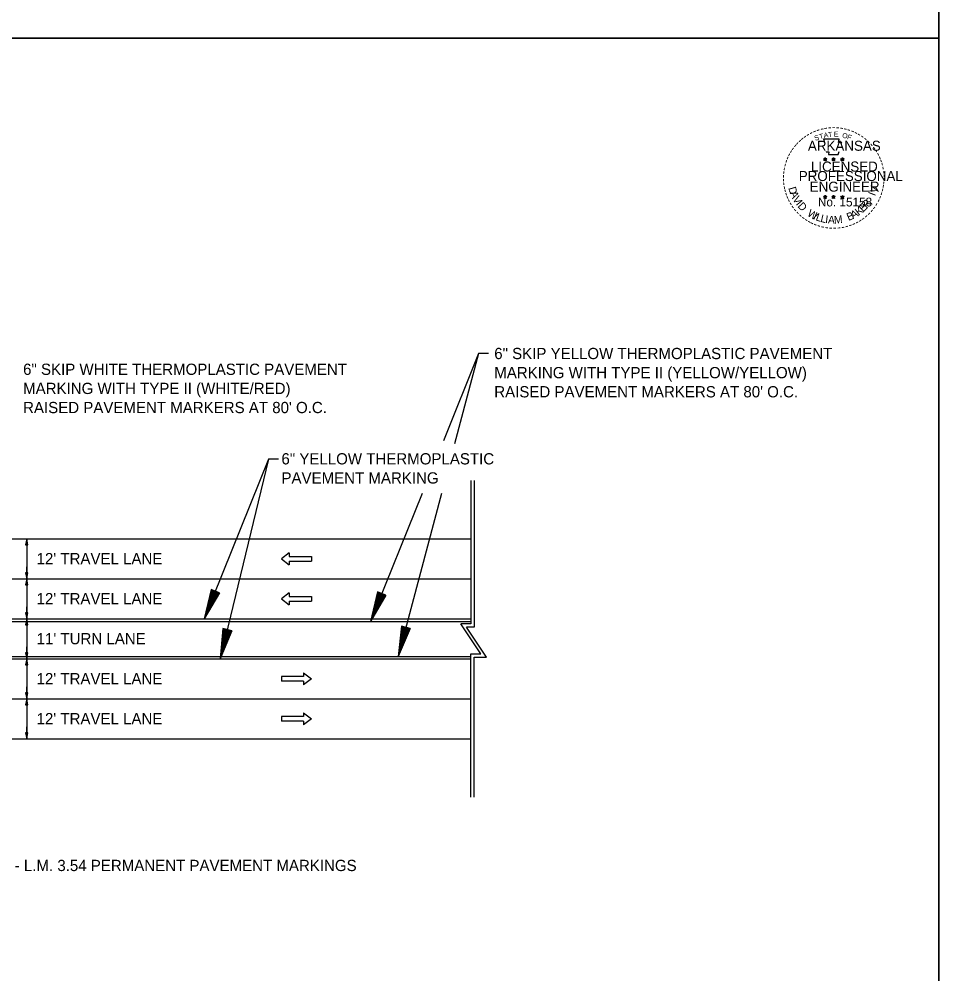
# Model space of a CAD drawing. Extents: x 1373096 to 1373266, y 381130 to 381790.
# Drawn here: x 1373174 to 1373266, y 381366.6 to 381462.1 of the extents above; entities that cross this region are included whole.
import ezdxf

# ---------------------------------------------------------------- set-up
doc = ezdxf.new("R2010")
doc.units = 0
for name, color, linetype in [('Default', 7, 'Continuous'), ('DSN_DRFT_Junk-No-Plot', 7, 'Continuous'), ('R_Border PE', 7, 'Continuous'), ('R_Draft', 7, 'Continuous')]:
    doc.layers.add(name, color=color, linetype=linetype)

msp = doc.modelspace()

# ---------------------------------------------------------------- linework, layer by layer
at = {"layer": 'Default'}
for p, q in [((1373219.95, 381428.656), (1373216.424, 381419.917)), ((1373219.95, 381428.656), (1373217.551, 381419.618)), ((1373220.95, 381428.656), (1373219.95, 381428.656)), ((1373198.936, 381418.092), (1373192.496, 381402.128)), ((1373198.936, 381418.092), (1373194.121, 381398.128)), ((1373199.936, 381418.092), (1373198.936, 381418.092)), ((1373219.169, 381415.965), (1373219.169, 381401.628)), ((1373219.502, 381415.965), (1373219.502, 381401.295)), ((1373214.305, 381414.664), (1373209.147, 381401.878)), ((1373216.238, 381414.671), (1373211.913, 381398.378)), ((1373201.021, 381408.728), (1373200.242, 381408.128)), ((1373201.021, 381408.728), (1373201.021, 381408.353)), ((1373200.242, 381408.128), (1373201.021, 381407.528)), ((1373201.021, 381408.353), (1373203.227, 381408.353)), ((1373201.021, 381407.903), (1373203.227, 381407.903)), ((1373201.021, 381407.903), (1373201.021, 381407.528)), ((1373203.227, 381408.353), (1373203.227, 381407.903)), ((1373193.201, 381405.078), (1373192.496, 381402.128)), ((1373193.271, 381405.05), (1373192.684, 381402.593)), ((1373193.342, 381405.022), (1373192.877, 381403.071)), ((1373193.411, 381404.994), (1373193.064, 381403.534)), ((1373194.036, 381404.742), (1373193.201, 381405.078)), ((1373193.482, 381404.965), (1373193.254, 381404.006)), ((1373193.553, 381404.936), (1373193.441, 381404.47)), ((1373193.684, 381404.884), (1373193.441, 381404.47)), ((1373194.036, 381404.742), (1373192.496, 381402.128)), ((1373193.966, 381404.77), (1373192.684, 381402.593)), ((1373193.895, 381404.798), (1373192.877, 381403.071)), ((1373193.826, 381404.826), (1373193.064, 381403.534)), ((1373193.754, 381404.856), (1373193.254, 381404.006)), ((1373201.021, 381404.728), (1373200.242, 381404.128)), ((1373200.242, 381404.128), (1373201.021, 381403.528)), ((1373201.021, 381404.728), (1373201.021, 381404.353)), ((1373201.021, 381404.353), (1373203.227, 381404.353)), ((1373203.227, 381404.353), (1373203.227, 381403.903)), ((1373209.852, 381404.828), (1373209.147, 381401.878)), ((1373210.687, 381404.492), (1373209.147, 381401.878)), ((1373209.922, 381404.8), (1373209.334, 381402.343)), ((1373210.617, 381404.52), (1373209.334, 381402.343)), ((1373209.993, 381404.772), (1373209.528, 381402.821)), ((1373210.546, 381404.548), (1373209.528, 381402.821)), ((1373210.062, 381404.744), (1373209.714, 381403.284)), ((1373210.477, 381404.576), (1373209.714, 381403.284)), ((1373210.687, 381404.492), (1373209.852, 381404.828)), ((1373210.133, 381404.715), (1373209.905, 381403.756)), ((1373210.404, 381404.606), (1373209.905, 381403.756)), ((1373210.204, 381404.686), (1373210.092, 381404.22)), ((1373210.335, 381404.634), (1373210.092, 381404.22)), ((1373201.021, 381403.903), (1373203.227, 381403.903)), ((1373201.021, 381403.903), (1373201.021, 381403.528)), ((1373194.387, 381401.15), (1373194.121, 381398.128)), ((1373194.46, 381401.132), (1373194.239, 381398.615)), ((1373194.535, 381401.114), (1373194.36, 381399.117)), ((1373195.262, 381400.939), (1373194.387, 381401.15)), ((1373194.608, 381401.097), (1373194.477, 381399.602)), ((1373194.682, 381401.079), (1373194.596, 381400.096)), ((1373212.248, 381401.393), (1373211.913, 381398.378)), ((1373213.118, 381401.162), (1373211.913, 381398.378)), ((1373212.32, 381401.374), (1373212.042, 381398.862)), ((1373213.045, 381401.181), (1373212.042, 381398.862)), ((1373212.394, 381401.354), (1373212.174, 381399.361)), ((1373212.971, 381401.201), (1373212.174, 381399.361)), ((1373213.118, 381401.162), (1373212.248, 381401.393)), ((1373212.467, 381401.335), (1373212.302, 381399.844)), ((1373212.899, 381401.22), (1373212.302, 381399.844)), ((1373212.541, 381401.315), (1373212.433, 381400.335)), ((1373212.823, 381401.24), (1373212.433, 381400.335)), ((1373212.615, 381401.296), (1373212.561, 381400.819)), ((1373212.751, 381401.259), (1373212.561, 381400.819)), ((1373219.169, 381401.628), (1373218.169, 381401.628)), ((1373220.169, 381398.628), (1373218.169, 381401.628)), ((1373220.725, 381398.295), (1373218.725, 381401.295)), ((1373219.502, 381401.295), (1373218.725, 381401.295)), ((1373195.262, 381400.939), (1373194.121, 381398.128)), ((1373195.189, 381400.956), (1373194.239, 381398.615)), ((1373195.115, 381400.974), (1373194.36, 381399.117)), ((1373195.042, 381400.992), (1373194.477, 381399.602)), ((1373194.966, 381401.01), (1373194.596, 381400.096)), ((1373194.756, 381401.061), (1373194.714, 381400.583)), ((1373194.893, 381401.028), (1373194.714, 381400.583)), ((1373219.169, 381384.291), (1373219.169, 381398.628)), ((1373219.169, 381398.628), (1373220.169, 381398.628)), ((1373219.502, 381384.291), (1373219.502, 381398.295)), ((1373219.502, 381398.295), (1373220.725, 381398.295)), ((1373202.449, 381396.353), (1373200.242, 381396.353)), ((1373200.242, 381396.353), (1373200.242, 381395.903)), ((1373202.449, 381396.728), (1373202.449, 381396.353)), ((1373202.449, 381396.728), (1373203.227, 381396.128)), ((1373202.449, 381395.903), (1373200.242, 381395.903)), ((1373203.227, 381396.128), (1373202.449, 381395.528)), ((1373202.449, 381395.903), (1373202.449, 381395.528)), ((1373202.449, 381392.728), (1373202.449, 381392.353)), ((1373202.449, 381392.728), (1373203.227, 381392.128)), ((1373202.449, 381392.353), (1373200.242, 381392.353)), ((1373200.242, 381392.353), (1373200.242, 381391.903)), ((1373202.449, 381391.903), (1373200.242, 381391.903)), ((1373203.227, 381392.128), (1373202.449, 381391.528)), ((1373202.449, 381391.903), (1373202.449, 381391.528))]:
    msp.add_line(p, q, dxfattribs=at)
for points in [[(1373095.974, 381570.174), (1373095.974, 381460.174), (1373265.974, 381460.174), (1373265.974, 381570.174)], [(1373095.974, 381460.174), (1373095.974, 381350.174), (1373265.974, 381350.174), (1373265.974, 381460.174)]]:
    msp.add_lwpolyline(points, close=True, dxfattribs=at)
at = {"layer": 'DSN_DRFT_Junk-No-Plot'}
msp.add_line((1373174.763, 381410.128), (1373174.763, 381390.154), dxfattribs=at)
for points in [[(1373095.974, 381570.174), (1373265.974, 381570.174), (1373265.974, 381460.174), (1373095.974, 381460.174)], [(1373095.974, 381570.174), (1373095.974, 381460.174), (1373265.974, 381460.174), (1373265.974, 381570.174)], [(1373095.974, 381460.174), (1373265.974, 381460.174), (1373265.974, 381350.174), (1373095.974, 381350.174)], [(1373095.974, 381460.174), (1373095.974, 381350.174), (1373265.974, 381350.174), (1373265.974, 381460.174)]]:
    msp.add_lwpolyline(points, close=True, dxfattribs=at)
for points in [[(1373174.763, 381410.128), (1373174.643, 381409.528), (1373174.883, 381409.528), (1373174.763, 381410.128), (1373174.763, 381408.928)], [(1373174.763, 381406.128), (1373174.883, 381406.728), (1373174.643, 381406.728), (1373174.763, 381406.128), (1373174.763, 381407.328)], [(1373174.763, 381406.128), (1373174.643, 381405.528), (1373174.883, 381405.528), (1373174.763, 381406.128), (1373174.763, 381404.928)], [(1373174.763, 381402.128), (1373174.883, 381402.728), (1373174.643, 381402.728), (1373174.763, 381402.128), (1373174.763, 381403.328)], [(1373174.763, 381402.128), (1373174.643, 381401.528), (1373174.883, 381401.528), (1373174.763, 381402.128), (1373174.763, 381400.928)], [(1373174.763, 381398.128), (1373174.883, 381398.728), (1373174.643, 381398.728), (1373174.763, 381398.128), (1373174.763, 381399.328)], [(1373174.763, 381398.128), (1373174.643, 381397.528), (1373174.883, 381397.528), (1373174.763, 381398.128), (1373174.763, 381396.928)], [(1373174.763, 381394.128), (1373174.883, 381394.728), (1373174.643, 381394.728), (1373174.763, 381394.128), (1373174.763, 381395.328)], [(1373174.763, 381394.128), (1373174.643, 381393.528), (1373174.883, 381393.528), (1373174.763, 381394.128), (1373174.763, 381392.928)], [(1373174.763, 381390.128), (1373174.883, 381390.728), (1373174.643, 381390.728), (1373174.763, 381390.128), (1373174.763, 381391.328)]]:
    msp.add_lwpolyline(points, dxfattribs=at)
at = {"layer": 'R_Border PE'}
for p, q in [((1373254.429, 381448.13), (1373254.603, 381448.074)), ((1373254.429, 381448.13), (1373254.555, 381448.107)), ((1373254.429, 381448.13), (1373254.547, 381448.069)), ((1373254.495, 381447.926), (1373254.603, 381448.074)), ((1373254.495, 381447.926), (1373254.558, 381448.048)), ((1373254.495, 381447.926), (1373254.602, 381448.034)), ((1373254.603, 381448.257), (1373254.583, 381448.131)), ((1373254.71, 381447.926), (1373254.602, 381448.033)), ((1373254.603, 381448.074), (1373254.603, 381448.257)), ((1373254.603, 381448.257), (1373254.628, 381448.132)), ((1373254.777, 381448.13), (1373254.603, 381448.074)), ((1373254.71, 381447.926), (1373254.603, 381448.074)), ((1373254.777, 381448.13), (1373254.634, 381448.105)), ((1373254.71, 381447.926), (1373254.641, 381448.071)), ((1373254.777, 381448.13), (1373254.675, 381448.079)), ((1373255.264, 381448.13), (1373255.438, 381448.074)), ((1373255.264, 381448.13), (1373255.39, 381448.107)), ((1373255.264, 381448.13), (1373255.382, 381448.069)), ((1373255.33, 381447.926), (1373255.438, 381448.074)), ((1373255.33, 381447.926), (1373255.393, 381448.048)), ((1373255.33, 381447.926), (1373255.437, 381448.034)), ((1373255.438, 381448.257), (1373255.418, 381448.131)), ((1373255.545, 381447.926), (1373255.437, 381448.033)), ((1373255.438, 381448.074), (1373255.438, 381448.257)), ((1373255.438, 381448.257), (1373255.463, 381448.132)), ((1373255.612, 381448.13), (1373255.438, 381448.074)), ((1373255.545, 381447.926), (1373255.438, 381448.074)), ((1373255.612, 381448.13), (1373255.469, 381448.105)), ((1373255.545, 381447.926), (1373255.476, 381448.071)), ((1373255.612, 381448.13), (1373255.51, 381448.079)), ((1373256.146, 381448.124), (1373256.32, 381448.068)), ((1373256.146, 381448.124), (1373256.272, 381448.101)), ((1373256.146, 381448.124), (1373256.264, 381448.063)), ((1373256.212, 381447.92), (1373256.32, 381448.068)), ((1373256.212, 381447.92), (1373256.275, 381448.042)), ((1373256.212, 381447.92), (1373256.319, 381448.028)), ((1373256.32, 381448.251), (1373256.3, 381448.125)), ((1373256.427, 381447.92), (1373256.319, 381448.027)), ((1373256.32, 381448.068), (1373256.32, 381448.251)), ((1373256.32, 381448.251), (1373256.345, 381448.126)), ((1373256.494, 381448.124), (1373256.32, 381448.068)), ((1373256.427, 381447.92), (1373256.32, 381448.068)), ((1373256.494, 381448.124), (1373256.351, 381448.099)), ((1373256.427, 381447.92), (1373256.358, 381448.065)), ((1373256.494, 381448.124), (1373256.392, 381448.073)), ((1373254.427, 381444.343), (1373254.601, 381444.288)), ((1373254.427, 381444.343), (1373254.553, 381444.321)), ((1373254.427, 381444.343), (1373254.545, 381444.282)), ((1373254.493, 381444.139), (1373254.601, 381444.288)), ((1373254.493, 381444.139), (1373254.556, 381444.261)), ((1373254.493, 381444.139), (1373254.6, 381444.248)), ((1373254.601, 381444.47), (1373254.581, 381444.344)), ((1373254.708, 381444.139), (1373254.6, 381444.246)), ((1373254.601, 381444.288), (1373254.601, 381444.47)), ((1373254.601, 381444.47), (1373254.626, 381444.345)), ((1373254.775, 381444.343), (1373254.601, 381444.288)), ((1373254.708, 381444.139), (1373254.601, 381444.288)), ((1373254.775, 381444.343), (1373254.632, 381444.319)), ((1373254.708, 381444.139), (1373254.639, 381444.285)), ((1373254.775, 381444.343), (1373254.673, 381444.292)), ((1373255.261, 381444.343), (1373255.436, 381444.288)), ((1373255.261, 381444.343), (1373255.388, 381444.321)), ((1373255.261, 381444.343), (1373255.38, 381444.282)), ((1373255.328, 381444.139), (1373255.436, 381444.288)), ((1373255.328, 381444.139), (1373255.391, 381444.261)), ((1373255.328, 381444.139), (1373255.435, 381444.248)), ((1373255.436, 381444.47), (1373255.415, 381444.344)), ((1373255.542, 381444.139), (1373255.435, 381444.246)), ((1373255.436, 381444.288), (1373255.436, 381444.47)), ((1373255.436, 381444.47), (1373255.46, 381444.345)), ((1373255.609, 381444.343), (1373255.436, 381444.288)), ((1373255.542, 381444.139), (1373255.436, 381444.288)), ((1373255.609, 381444.343), (1373255.466, 381444.319)), ((1373255.542, 381444.139), (1373255.474, 381444.285)), ((1373255.609, 381444.343), (1373255.507, 381444.292)), ((1373256.145, 381444.338), (1373256.319, 381444.283)), ((1373256.145, 381444.338), (1373256.271, 381444.316)), ((1373256.145, 381444.338), (1373256.263, 381444.277)), ((1373256.211, 381444.134), (1373256.319, 381444.283)), ((1373256.211, 381444.134), (1373256.274, 381444.256)), ((1373256.211, 381444.134), (1373256.318, 381444.243)), ((1373256.319, 381444.465), (1373256.299, 381444.339)), ((1373256.426, 381444.134), (1373256.318, 381444.241)), ((1373256.319, 381444.283), (1373256.319, 381444.465)), ((1373256.319, 381444.465), (1373256.344, 381444.34)), ((1373256.493, 381444.338), (1373256.319, 381444.283)), ((1373256.426, 381444.134), (1373256.319, 381444.283)), ((1373256.493, 381444.338), (1373256.35, 381444.314)), ((1373256.426, 381444.134), (1373256.357, 381444.28)), ((1373256.493, 381444.338), (1373256.391, 381444.287))]:
    msp.add_line(p, q, dxfattribs=at)
for points in [[(1373254.449, 381450.069), (1373254.584, 381449.655)], [(1373256.205, 381449.608), (1373256.276, 381449.75), (1373255.933, 381449.738), (1373256.007, 381450.069), (1373254.449, 381450.069)], [(1373254.695, 381448.857), (1373254.695, 381448.814), (1373254.977, 381448.804), (1373254.95, 381448.568), (1373255.885, 381448.568), (1373255.985, 381448.836)], [(1373254.603, 381448.257), (1373254.71, 381447.926), (1373254.429, 381448.13), (1373254.777, 381448.13), (1373254.495, 381447.926), (1373254.603, 381448.257)], [(1373255.438, 381448.257), (1373255.545, 381447.926), (1373255.264, 381448.13), (1373255.612, 381448.13), (1373255.33, 381447.926), (1373255.438, 381448.257)], [(1373256.32, 381448.251), (1373256.427, 381447.92), (1373256.146, 381448.124), (1373256.494, 381448.124), (1373256.212, 381447.92), (1373256.32, 381448.251)], [(1373254.601, 381444.47), (1373254.708, 381444.139), (1373254.427, 381444.343), (1373254.775, 381444.343), (1373254.493, 381444.139), (1373254.601, 381444.47)], [(1373255.436, 381444.47), (1373255.542, 381444.139), (1373255.261, 381444.343), (1373255.609, 381444.343), (1373255.328, 381444.139), (1373255.436, 381444.47)], [(1373256.319, 381444.465), (1373256.426, 381444.134), (1373256.145, 381444.338), (1373256.493, 381444.338), (1373256.211, 381444.134), (1373256.319, 381444.465)]]:
    msp.add_lwpolyline(points, dxfattribs=at)
for centre, radius in [((1373254.603, 381448.074), 0.0861), ((1373254.603, 381448.074), 0.0723), ((1373254.603, 381448.074), 0.0579), ((1373254.603, 381448.074), 0.0495), ((1373254.603, 381448.074), 0.0374), ((1373254.603, 381448.074), 0.0248), ((1373254.603, 381448.074), 0.0148), ((1373255.438, 381448.074), 0.0861), ((1373255.438, 381448.074), 0.0723), ((1373255.438, 381448.074), 0.0579), ((1373255.438, 381448.074), 0.0495), ((1373255.438, 381448.074), 0.0374), ((1373255.438, 381448.074), 0.0248), ((1373255.438, 381448.074), 0.0148), ((1373256.32, 381448.068), 0.0861), ((1373256.32, 381448.068), 0.0723), ((1373256.32, 381448.068), 0.0579), ((1373256.32, 381448.068), 0.0495), ((1373256.32, 381448.068), 0.0374), ((1373256.32, 381448.068), 0.0248), ((1373256.32, 381448.068), 0.0148), ((1373254.601, 381444.287), 0.0861), ((1373254.601, 381444.287), 0.0723), ((1373254.601, 381444.287), 0.0579), ((1373254.601, 381444.287), 0.0495), ((1373254.601, 381444.287), 0.0374), ((1373254.601, 381444.287), 0.0248), ((1373254.601, 381444.287), 0.0148), ((1373255.435, 381444.287), 0.0861), ((1373255.435, 381444.287), 0.0723), ((1373255.435, 381444.287), 0.0579), ((1373255.435, 381444.287), 0.0495), ((1373255.435, 381444.287), 0.0374), ((1373255.435, 381444.287), 0.0248), ((1373255.435, 381444.287), 0.0148), ((1373256.319, 381444.282), 0.0861), ((1373256.319, 381444.282), 0.0723), ((1373256.319, 381444.282), 0.0579), ((1373256.319, 381444.282), 0.0495), ((1373256.319, 381444.282), 0.0374), ((1373256.319, 381444.282), 0.0248), ((1373256.319, 381444.282), 0.0148)]:
    msp.add_circle(centre, radius, dxfattribs=at)
at = {"layer": 'R_Draft'}
for p, q in [((1373142.778, 381410.128), (1373219.169, 381410.128)), ((1373142.778, 381406.128), (1373219.169, 381406.128)), ((1373142.778, 381402.128), (1373219.169, 381402.128)), ((1373142.778, 381401.878), (1373219.169, 381401.878)), ((1373142.778, 381398.378), (1373219.169, 381398.378)), ((1373142.778, 381398.128), (1373219.169, 381398.128)), ((1373142.778, 381394.128), (1373219.169, 381394.128)), ((1373142.778, 381390.128), (1373219.169, 381390.128))]:
    msp.add_line(p, q, dxfattribs=at)

# ---------------------------------------------------------------- texts
at = {"layer": 'Default'}
for s, p in [('6" SKIP YELLOW THERMOPLASTIC PAVEMENT', (1373221.513, 381428.094)), ('6" SKIP WHITE THERMOPLASTIC PAVEMENT', (1373174.403, 381426.517)), ('MARKING WITH TYPE II (YELLOW/YELLOW)', (1373221.513, 381426.181)), ('MARKING WITH TYPE II (WHITE/RED)', (1373174.403, 381424.605)), ("RAISED PAVEMENT MARKERS AT 80' O.C.", (1373221.513, 381424.269)), ("RAISED PAVEMENT MARKERS AT 80' O.C.", (1373174.403, 381422.693)), ('6" YELLOW THERMOPLASTIC', (1373200.237, 381417.566)), ('PAVEMENT MARKING', (1373200.237, 381415.653))]:
    msp.add_text(s, height=1.125, dxfattribs=at).set_placement(p)
at = {"layer": 'R_Border PE'}
for s, height, rotation, p in [('-', 0.8, 28.79182, (1373253.189, 381450.339)), ('-', 0.8, 24.30721, (1373253.506, 381450.498)), ('-', 0.8, 19.17608, (1373253.823, 381450.632)), ('-', 0.8, 13.63015, (1373254.198, 381450.753)), ('A', 0.5, 11.21318, (1373254.496, 381450.199)), ('-', 0.8, 10.21935, (1373254.537, 381450.834)), ('T', 0.5, 6.02276, (1373254.921, 381450.282)), ('-', 0.8, 5.89682, (1373254.901, 381450.889)), ('-', 0.8, 0.18623, (1373255.287, 381450.925)), ('E', 0.5, 0.83234, (1373255.473, 381450.337)), ('-', 0.8, 357.74304, (1373255.649, 381450.918)), ('-', 0.8, 352.16172, (1373256.021, 381450.89)), ('O', 0.5, 350.4515, (1373256.275, 381450.232)), ('-', 0.8, 347.20489, (1373256.38, 381450.833)), ('-', 0.8, 342.3362, (1373256.698, 381450.756)), ('-', 0.8, 337.85509, (1373257.065, 381450.644)), ('-', 0.8, 334.12109, (1373257.381, 381450.509)), ('-', 0.8, 48.42305, (1373251.923, 381449.32)), ('-', 0.8, 42.96224, (1373252.147, 381449.559)), ('-', 0.8, 38.95066, (1373252.364, 381449.768)), ('-', 0.8, 36.23174, (1373252.602, 381449.957)), ('-', 0.8, 34.06357, (1373252.891, 381450.154)), ('S', 0.5, 21.59401, (1373253.626, 381449.908)), ('T', 0.5, 16.4036, (1373254.083, 381450.073)), ('F', 0.5, 340.07066, (1373256.752, 381450.118)), ('-', 0.8, 329.64089, (1373257.67, 381450.367)), ('-', 0.8, 325.86266, (1373257.992, 381450.187)), ('-', 0.8, 320.52971, (1373258.297, 381449.974)), ('-', 0.8, 315.57859, (1373258.596, 381449.73)), ('-', 0.8, 58.07063, (1373251.353, 381448.53)), ('-', 0.8, 54.23247, (1373251.515, 381448.794)), ('-', 0.8, 50.61418, (1373251.722, 381449.077)), ('-', 0.8, 309.87973, (1373258.881, 381449.455)), ('-', 0.8, 306.65218, (1373259.143, 381449.154)), ('-', 0.7, 303.67529, (1373259.386, 381448.87)), ('-', 0.8, 72.39447, (1373250.957, 381447.603)), ('-', 0.8, 67.77427, (1373251.067, 381447.918)), ('-', 0.8, 62.87135, (1373251.196, 381448.223)), ('-', 0.8, 299.66835, (1373259.546, 381448.566)), ('-', 0.8, 294.66279, (1373259.708, 381448.26)), ('-', 0.8, 290.57283, (1373259.836, 381447.972)), ('-', 0.8, 81.20126, (1373250.793, 381446.889)), ('-', 0.8, 75.46096, (1373250.859, 381447.246)), ('-', 0.8, 285.12326, (1373259.953, 381447.682)), ('-', 0.8, 280.54934, (1373260.053, 381447.311)), ('-', 0.8, 276.59616, (1373260.134, 381446.927)), ('-', 0.8, 94.19588, (1373250.76, 381445.831)), ('-', 0.8, 89.06224, (1373250.742, 381446.193)), ('-', 0.8, 85.18634, (1373250.755, 381446.544)), ('-', 0.8, 274.33011, (1373260.164, 381446.566)), ('-', 0.8, 269.94067, (1373260.181, 381446.25)), ('-', 0.8, 98.94793, (1373250.796, 381445.497)), ('-', 0.8, 101.71495, (1373250.863, 381445.131)), ('-', 0.8, 105.45785, (1373250.944, 381444.833)), ('D', 0.77, 286.28478, (1373250.908, 381445.2)), ('V', 0.77, 72.65729, (1373259.704, 381444.619)), ('-', 0.8, 255.7626, (1373260.081, 381445.251)), ('-', 0.8, 260.99529, (1373260.136, 381445.59)), ('-', 0.8, 263.5172, (1373260.172, 381445.917)), ('-', 0.8, 109.08742, (1373251.052, 381444.518)), ('-', 0.8, 114.06432, (1373251.179, 381444.22)), ('-', 0.8, 115.72885, (1373251.331, 381443.911)), ('A', 0.77, 292.78351, (1373251.054, 381444.699)), ('V', 0.77, 300.79357, (1373251.311, 381444.109)), ('R', 0.77, 50.36514, (1373258.768, 381443.105)), ('I', 0.77, 69.03009, (1373259.593, 381444.35)), ('-', 0.8, 244.61971, (1373259.748, 381444.24)), ('-', 0.8, 247.88866, (1373259.879, 381444.554)), ('-', 0.8, 252.86809, (1373259.991, 381444.891)), ('-', 0.8, 120.44712, (1373251.51, 381443.618)), ('-', 0.8, 125.89344, (1373251.711, 381443.337)), ('-', 0.8, 130.71812, (1373251.942, 381443.061)), ('I', 0.77, 308.35023, (1373251.627, 381443.591)), ('D', 0.77, 311.97742, (1373251.802, 381443.358)), ('W', 0.77, 328.07311, (1373252.741, 381442.475)), ('K', 0.77, 36.91429, (1373257.946, 381442.407)), ('E', 0.77, 44.01755, (1373258.4, 381442.752)), (',', 0.77, 57.4684, (1373259.129, 381443.547)), ('-', 0.8, 233.84524, (1373259.35, 381443.537)), ('-', 0.8, 239.07125, (1373259.551, 381443.864)), ('-', 0.8, 134.22381, (1373252.201, 381442.789)), ('-', 0.8, 138.93382, (1373252.463, 381442.557)), ('-', 0.8, 144.64634, (1373252.741, 381442.354)), ('I', 0.77, 336.6877, (1373253.335, 381442.12)), ('L', 0.77, 340.3149, (1373253.6, 381441.998)), ('L', 0.77, 346.66249, (1373254.079, 381441.826)), ('I', 0.77, 353.01009, (1373254.575, 381441.707)), ('A', 0.77, 356.63729, (1373254.864, 381441.665)), ('M', 0.77, 4.64735, (1373255.506, 381441.636)), ('B', 0.77, 22.8589, (1373256.939, 381441.901)), ('A', 0.77, 28.90423, (1373257.387, 381442.088)), ('-', 0.8, 215.73633, (1373258.36, 381442.482)), ('-', 0.8, 221.08509, (1373258.635, 381442.718)), ('-', 0.8, 225.76533, (1373258.896, 381442.972)), ('-', 0.8, 231.25377, (1373259.135, 381443.254)), ('-', 0.8, 148.08978, (1373253.022, 381442.168)), ('-', 0.8, 151.57039, (1373253.311, 381442.006)), ('-', 0.8, 154.60019, (1373253.572, 381441.882)), ('-', 0.8, 158.56121, (1373253.884, 381441.755)), ('-', 0.8, 162.79826, (1373254.228, 381441.649)), ('-', 0.8, 167.55551, (1373254.585, 381441.567)), ('-', 0.8, 173.11546, (1373254.971, 381441.512)), ('-', 0.8, 176.51827, (1373255.345, 381441.485)), ('-', 0.8, 181.59176, (1373255.717, 381441.495)), ('-', 0.8, 185.81666, (1373256.122, 381441.533)), ('-', 0.8, 191.28576, (1373256.49, 381441.599)), ('-', 0.8, 195.47429, (1373256.854, 381441.698)), ('-', 0.8, 199.46435, (1373257.187, 381441.817)), ('-', 0.8, 204.25161, (1373257.502, 381441.956)), ('-', 0.8, 207.35684, (1373257.814, 381442.115)), ('-', 0.8, 212.24909, (1373258.093, 381442.288))]:
    msp.add_text(s, height=height, rotation=rotation, dxfattribs=at).set_placement(p)
for s, height, p in [('ARKANSAS', 1, (1373252.875, 381448.925)), ('LICENSED', 1, (1373253.174, 381446.85)), ('PROFESSIONAL', 1, (1373251.962, 381445.898)), ('ENGINEER', 1, (1373253.056, 381444.836)), ('No. 15158', 0.8785, (1373253.877, 381443.36)), ('AAMU', 0.00001, (1373255.402, 381441.633))]:
    msp.add_text(s, height=height, dxfattribs=at).set_placement(p)
at = {"layer": 'R_Draft'}
for s, p in [("12' TRAVEL LANE", (1373175.752, 381407.586)), ("12' TRAVEL LANE", (1373175.752, 381403.586)), ("11' TURN LANE", (1373175.76, 381399.586)), ("12' TRAVEL LANE", (1373175.752, 381395.586)), ("12' TRAVEL LANE", (1373175.752, 381391.586)), ('HWY. 64 SECTION 9 L.M. 3.36 - L.M. 3.54 PERMANENT PAVEMENT MARKINGS', (1373152.078, 381376.91))]:
    msp.add_text(s, height=1.125, dxfattribs=at).set_placement(p)

doc.saveas('drawing.dxf')
